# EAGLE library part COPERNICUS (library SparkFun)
Copernicus Massively edited and tweaked footprint to meet the Trimble recommended layout and paste layer. Footprint production proven. Spark Fun Electronics SKU : GPS-Copernicus
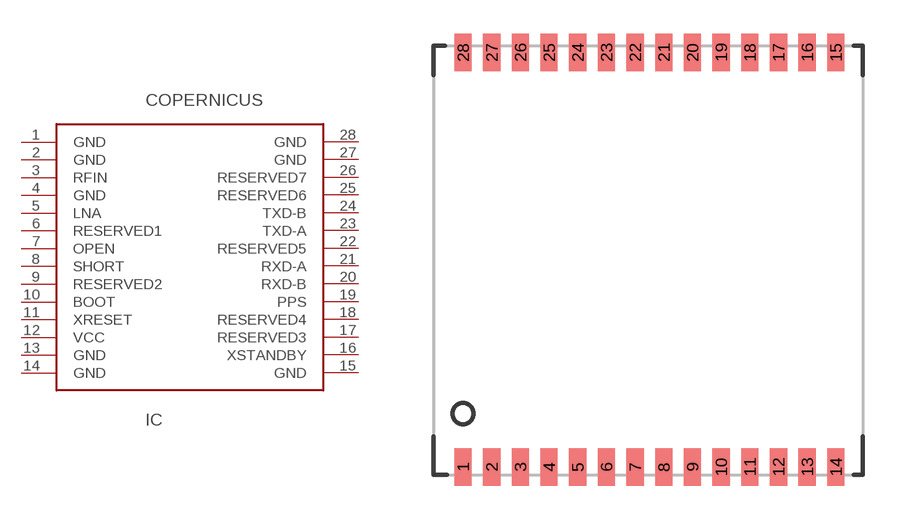
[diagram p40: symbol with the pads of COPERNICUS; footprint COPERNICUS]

Designator prefix IC

## COPERNICUSSMD  [COPERNICUS]
1  GND
2  GND
3  RFIN
4  GND
5  LNA
6  RESERVED1
7  OPEN
8  SHORT
9  RESERVED2
10  BOOT
11  XRESET
12  VCC
13  GND
14  GND
15  GND
16  XSTANDBY
17  RESERVED3
18  RESERVED4
19  PPS
20  RXD-B
21  RXD-A
22  RESERVED5
23  TXD-A
24  TXD-B
25  RESERVED6
26  RESERVED7
27  GND
28  GND

## Footprint COPERNICUS (pad centres in mm)
smd 0.762 x 1.651: 1 0,-18.364; 2 1.27,-18.364; 3 2.54,-18.364; 4 3.81,-18.364; 5 5.08,-18.364; 6 6.35,-18.364; 7 7.62,-18.364; 8 8.89,-18.364; 9 10.16,-18.364; 10 11.43,-18.364; 11 12.7,-18.364; 12 13.97,-18.364; 13 15.24,-18.364; 14 16.51,-18.364; 15 16.51,0; 16 15.24,0; 17 13.97,0; 18 12.7,0; 19 11.43,0; 20 10.16,0; 21 8.89,0; 22 7.62,0; 23 6.35,0; 24 5.08,0; 25 3.81,0; 26 2.54,0; 27 1.27,0; 28 0,0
